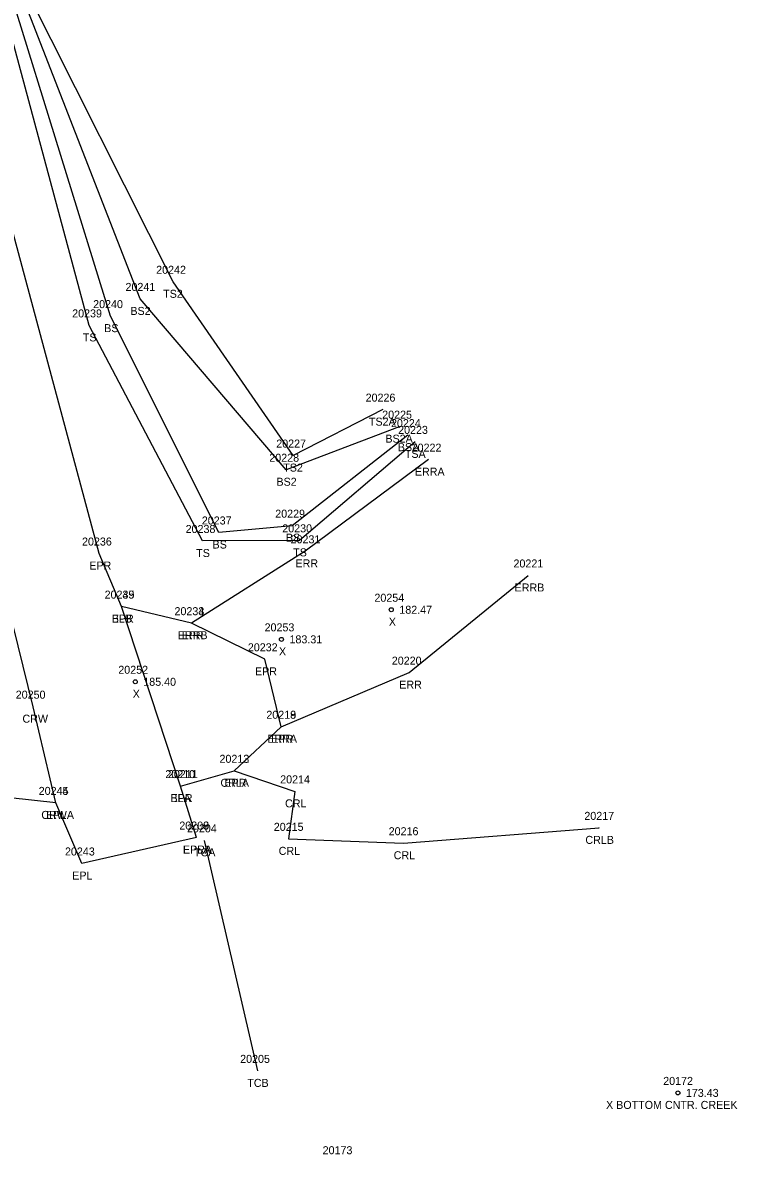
# Model space of a CAD drawing. Extents: x 2077883 to 2078272, y 787819 to 788945.
# Drawn here: x 2078085.4 to 2078174.7, y 788381.3 to 788522.7 of the extents above; entities that cross this region are included whole.
import ezdxf

# ---------------------------------------------------------------- set-up
doc = ezdxf.new("R2010")
doc.units = 0
for name, color, linetype in [('Default', 7, 'Continuous'), ('RD_DTM_BkLn1', 7, 'Continuous'), ('RD_DTM_BkLn2', 7, 'Continuous'), ('RD_EX_H2O', 7, 'Continuous'), ('RD_EX_H2O_txCode', 7, 'Continuous'), ('RD_EX_Road', 7, 'Continuous'), ('RD_EX_Road_txCode', 7, 'Continuous'), ('RD_Sketch8', 7, 'Continuous'), ('RD_SMD_Locator', 7, 'Continuous'), ('RD_SMD_Misc', 7, 'Continuous')]:
    doc.layers.add(name, color=color, linetype=linetype)

msp = doc.modelspace()

# ---------------------------------------------------------------- linework, layer by layer
at = {"layer": 'Default'}
msp.add_line((2078108.1, 788420.51), (2078114.73, 788391.71), dxfattribs=at)
for centre in [(2078108.1, 788420.51), (2078114.73, 788391.71)]:
    msp.add_circle(centre, 0.001, dxfattribs=at)
at = {"layer": 'RD_DTM_BkLn1'}
msp.add_line((2078105.11, 788427.29), (2078097.77, 788449.71), dxfattribs=at)
msp.add_lwpolyline([(2078089.54, 788425.19), (2078086.71, 788437.21), (2078062.2, 788536.79), (2078033.97, 788636.37), (2078001.1, 788734.32), (2077964.77, 788830.93), (2077924.88, 788926.7)], dxfattribs=at)
at = {"layer": 'RD_DTM_BkLn2'}
for points in [[(2078132.44, 788472.19), (2078118.34, 788466.81), (2078100.1, 788488.15), (2078085.17, 788526.48), (2078080.48, 788541.38), (2078063.7, 788600.7), (2078051.16, 788642.09), (2078017.07, 788740.46), (2077982.21, 788837.85), (2077942.69, 788934.33)], [(2078130.39, 788474.32), (2078119.21, 788468.58), (2078104.21, 788490.29), (2078085.93, 788526.63), (2078081.69, 788541.53), (2078065.4, 788601.95), (2078053.34, 788642.42), (2078018.45, 788740.81), (2077983.36, 788838.44), (2077944.78, 788934.86)], [(2078133.54, 788471.13), (2078119.08, 788459.82), (2078109.91, 788458.97), (2078096.37, 788486), (2078083.98, 788526.2), (2078079.55, 788541.15), (2078062.23, 788600.27), (2078049.45, 788641.41), (2078015.58, 788739.83), (2077979.12, 788836.63), (2077939.6, 788933.24)], [(2078134.43, 788470.29), (2078120, 788457.99), (2078107.89, 788457.91), (2078093.72, 788484.84), (2078082.52, 788526.41), (2078077.77, 788540.75), (2078060.01, 788599.41), (2078046.63, 788640.05), (2078012.72, 788738.62), (2077977.66, 788835.93), (2077936.62, 788932.18)]]:
    msp.add_lwpolyline(points, dxfattribs=at)
at = {"layer": 'RD_EX_H2O'}
msp.add_lwpolyline([(2078111.84, 788429.2), (2078119.42, 788426.63), (2078118.62, 788420.7), (2078132.99, 788420.15), (2078157.4, 788422.07)], dxfattribs=at)
at = {"layer": 'RD_EX_Road'}
for points in [[(2078107.13, 788420.86), (2078105.11, 788427.29), (2078111.84, 788429.2), (2078117.69, 788434.7), (2078115.66, 788443.13), (2078106.49, 788447.64), (2078097.77, 788449.71), (2078094.97, 788456.34), (2078072.64, 788539.43), (2078043.77, 788639.22), (2078010.2, 788737.35), (2077974.01, 788834.54), (2077934.07, 788930.86)], [(2078107.13, 788420.86), (2078092.81, 788417.62), (2078089.54, 788425.19), (2078083.84, 788425.84), (2078081.3, 788430.73), (2078074.53, 788432.67), (2078073.43, 788440.66), (2078071.07, 788452.5), (2078051.67, 788533.56), (2078023.01, 788633.14), (2078012.91, 788665.11), (2078004.86, 788689.7), (2077990.53, 788730.26), (2077954.65, 788827.14), (2077915.26, 788922.36)], [(2078136.12, 788468.07), (2078120.72, 788456.62), (2078106.49, 788447.64)], [(2078117.69, 788434.7), (2078133.68, 788441.46), (2078148.56, 788453.6)]]:
    msp.add_lwpolyline(points, dxfattribs=at)
at = {"layer": 'RD_SMD_Locator'}
for centre, radius in [((2078104.21, 788490.29), 0.001), ((2078100.1, 788488.15), 0.001), ((2078096.37, 788486), 0.001), ((2078093.72, 788484.84), 0.001), ((2078130.39, 788474.32), 0.001), ((2078132.44, 788472.19), 0.001), ((2078133.54, 788471.13), 0.001), ((2078134.43, 788470.29), 0.001), ((2078119.21, 788468.58), 0.001), ((2078136.12, 788468.07), 0.001), ((2078118.34, 788466.81), 0.001), ((2078109.91, 788458.97), 0.001), ((2078119.08, 788459.82), 0.001), ((2078107.89, 788457.91), 0.001), ((2078120, 788457.99), 0.001), ((2078094.97, 788456.34), 0.001), ((2078120.72, 788456.62), 0.001), ((2078148.56, 788453.6), 0.001), ((2078097.77, 788449.71), 0.001), ((2078097.77, 788449.71), 0.001), ((2078131.46, 788449.32), 0.25), ((2078106.49, 788447.64), 0.001), ((2078106.49, 788447.64), 0.001), ((2078117.74, 788445.62), 0.25), ((2078115.66, 788443.13), 0.001), ((2078099.48, 788440.32), 0.25), ((2078133.68, 788441.46), 0.001), ((2078086.71, 788437.21), 0.001), ((2078117.69, 788434.7), 0.001), ((2078117.69, 788434.7), 0.001), ((2078111.84, 788429.2), 0.001), ((2078111.84, 788429.2), 0.001), ((2078105.11, 788427.29), 0.001), ((2078105.11, 788427.29), 0.001), ((2078119.42, 788426.63), 0.001), ((2078089.54, 788425.19), 0.001), ((2078089.54, 788425.19), 0.001), ((2078157.4, 788422.07), 0.001), ((2078107.13, 788420.86), 0.001), ((2078107.13, 788420.86), 0.001), ((2078118.62, 788420.7), 0.001), ((2078132.99, 788420.15), 0.001), ((2078092.81, 788417.62), 0.001), ((2078167.25, 788388.96), 0.25)]:
    msp.add_circle(centre, radius, dxfattribs=at)

# ---------------------------------------------------------------- texts
at = {"layer": 'RD_EX_H2O_txCode'}
for s, p in [('20213', (2078110, 788430.2)), ('CRLA', (2078110.12, 788427.2)), ('20214', (2078117.58, 788427.63)), ('CRL', (2078118.19, 788424.63)), ('20217', (2078155.57, 788423.07)), ('20215', (2078116.78, 788421.7)), ('20216', (2078131.13, 788421.15)), ('CRLB', (2078155.7, 788420.07)), ('CRL', (2078117.39, 788418.7)), ('CRL', (2078131.76, 788418.15))]:
    msp.add_text(s, height=1, dxfattribs=at).set_placement(p)
at = {"layer": 'RD_EX_Road_txCode'}
for s, p in [('20222', (2078134, 788469.07)), ('ERRA', (2078134.4, 788466.07)), ('20236', (2078092.83, 788457.34)), ('20231', (2078118.88, 788457.62)), ('EPR', (2078093.74, 788454.34)), ('ERR', (2078119.49, 788454.62)), ('20221', (2078146.72, 788454.6)), ('ERRB', (2078146.86, 788451.6)), ('20235', (2078095.65, 788450.71)), ('20233', (2078104.38, 788448.64)), ('20234', (2078104.38, 788448.64)), ('EPR', (2078096.54, 788447.71)), ('ERRB', (2078104.79, 788445.64)), ('EPR', (2078105.27, 788445.64)), ('20232', (2078113.54, 788444.13)), ('20220', (2078131.52, 788442.46)), ('EPR', (2078114.43, 788441.13)), ('ERR', (2078132.45, 788439.46)), ('20218', (2078115.85, 788435.7)), ('20219', (2078115.85, 788435.7)), ('ERRA', (2078115.97, 788432.7)), ('EPR', (2078116.46, 788432.7)), ('20212', (2078110, 788430.2)), ('20210', (2078103.24, 788428.29)), ('EPR', (2078110.61, 788427.2)), ('20244', (2078087.42, 788426.19)), ('EPR', (2078103.89, 788425.29)), ('EPL', (2078088.33, 788423.19)), ('20208', (2078104.98, 788421.86)), ('20209', (2078104.98, 788421.86)), ('20243', (2078090.7, 788418.62)), ('EPRA', (2078105.42, 788418.86)), ('EPLA', (2078105.44, 788418.86)), ('EPL', (2078091.61, 788415.62))]:
    msp.add_text(s, height=1, dxfattribs=at).set_placement(p)
at = {"layer": 'RD_Sketch8'}
for s, p in [('20254', (2078129.35, 788450.32)), ('182.47', (2078132.46, 788448.82)), ('20253', (2078115.63, 788446.62)), ('X', (2078131.15, 788447.32)), ('183.31', (2078118.74, 788445.12)), ('X', (2078117.43, 788443.62)), ('20252', (2078097.36, 788441.32)), ('185.40', (2078100.48, 788439.82)), ('X', (2078099.16, 788438.32)), ('20172', (2078165.42, 788389.96)), ('173.43', (2078168.25, 788388.46)), ('X BOTTOM CNTR. CREEK', (2078158.28, 788386.96)), ('20173', (2078122.88, 788381.3))]:
    msp.add_text(s, height=1, dxfattribs=at).set_placement(p)
at = {"layer": 'RD_SMD_Misc'}
for s, p in [('20242', (2078102.09, 788491.29)), ('20241', (2078098.26, 788489.15)), ('TS2', (2078102.96, 788488.29)), ('20240', (2078094.22, 788487)), ('BS2', (2078098.87, 788486.15)), ('20239', (2078091.6, 788485.84)), ('BS', (2078095.6, 788484)), ('TS', (2078092.93, 788482.84)), ('20226', (2078128.25, 788475.32)), ('TS2A', (2078128.66, 788472.32)), ('20225', (2078130.32, 788473.19)), ('20224', (2078131.42, 788472.13)), ('20223', (2078132.31, 788471.29)), ('20227', (2078117.09, 788469.58)), ('BS2A', (2078130.72, 788470.19)), ('BSA', (2078132.27, 788469.13)), ('20228', (2078116.22, 788467.81)), ('TSA', (2078133.15, 788468.29)), ('TS2', (2078117.96, 788466.58)), ('BS2', (2078117.11, 788464.81)), ('20229', (2078116.96, 788460.82)), ('20237', (2078107.79, 788459.97)), ('20238', (2078105.77, 788458.91)), ('20230', (2078117.84, 788458.99)), ('BS', (2078118.3, 788457.82)), ('BS', (2078109.13, 788456.97)), ('TS', (2078107.09, 788455.91)), ('TS', (2078119.2, 788455.99)), ('20249', (2078095.65, 788450.71)), ('BLB', (2078096.54, 788447.71)), ('20250', (2078084.55, 788438.21)), ('CRW', (2078085.39, 788435.21)), ('20211', (2078103.56, 788428.29)), ('20245', (2078087.42, 788426.19)), ('BLA', (2078103.87, 788425.29)), ('CRWA', (2078087.74, 788423.19)), ('20204', (2078105.94, 788421.51)), ('TCA', (2078106.82, 788418.51)), ('20205', (2078112.58, 788392.71)), ('TCB', (2078113.47, 788389.71))]:
    msp.add_text(s, height=1, dxfattribs=at).set_placement(p)

doc.saveas('drawing.dxf')
